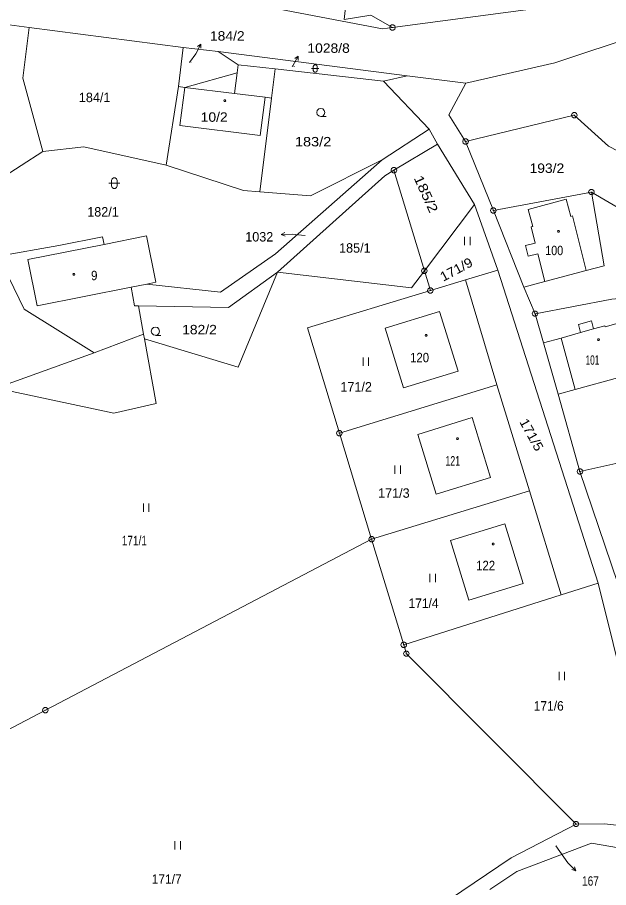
# Model space of a CAD drawing. Extents: x -687390 to -684106, y -954833 to -951648.
# Drawn here: x -686782.5 to -686675.9, y -952530.5 to -952373.7 of the extents above; entities that cross this region are included whole.
import ezdxf
from ezdxf.enums import TextEntityAlignment as Align

# ---------------------------------------------------------------- set-up
doc = ezdxf.new("R2010")
doc.units = 0
doc.header["$LTSCALE"] = 0.68
for name, color, linetype, lineweight in [('1', 7, 'Continuous', 13), ('3', 7, 'Continuous', 13), ('4', 7, 'Continuous', 13), ('5', 7, 'Continuous', 13), ('7', 7, 'Continuous', 13), ('8', 7, 'Continuous', 13)]:
    doc.layers.add(name, color=color, linetype=linetype, lineweight=lineweight)
doc.layers.add('2', color=7, linetype='Continuous')

msp = doc.modelspace()

# ---------------------------------------------------------------- linework, layer by layer
at = {"layer": '1'}
for p, q in [((-686714.84, -952375.47), (-686689.87, -952372.16)), ((-686785.8, -952374.77), (-686780.33, -952375.48)), ((-686753.44, -952386.12), (-686752.56, -952379.08)), ((-686752.56, -952379.08), (-686746.26, -952379.83)), ((-686742.67, -952382.2), (-686746.26, -952379.83)), ((-686746.26, -952379.83), (-686712.18, -952384.17)), ((-686735.98, -952382.95), (-686742.67, -952382.2)), ((-686735.98, -952382.95), (-686736.64, -952388.19)), ((-686716.46, -952385.15), (-686735.98, -952382.95)), ((-686716.46, -952385.15), (-686712.18, -952384.17)), ((-686712.18, -952384.17), (-686701.59, -952385.52)), ((-686755.64, -952400.32), (-686753.44, -952386.12)), ((-686752.26, -952386.27), (-686753.44, -952386.12)), ((-686736.64, -952388.19), (-686738.74, -952405.12)), ((-686696.66, -952408.48), (-686701.66, -952396.03)), ((-686716.7, -952399.34), (-686735.91, -952416.26)), ((-686755.64, -952400.32), (-686741.72, -952404.89)), ((-686738.74, -952405.12), (-686741.72, -952404.89)), ((-686729.62, -952405.8), (-686738.74, -952405.12)), ((-686696.66, -952408.48), (-686678.97, -952405.15)), ((-686676.68, -952418.44), (-686678.97, -952405.15)), ((-686700.05, -952407.36), (-686695.83, -952419.23)), ((-686691.17, -952422.3), (-686696.66, -952408.48)), ((-686757.52, -952421.4), (-686759.18, -952413.05)), ((-686745.82, -952423.17), (-686735.91, -952416.26)), ((-686679.93, -952419.3), (-686676.68, -952418.44)), ((-686708.01, -952422.9), (-686709.09, -952419.35)), ((-686695.83, -952419.23), (-686701.66, -952420.99)), ((-686677.75, -952475.63), (-686695.83, -952419.23)), ((-686679.93, -952419.3), (-686687.37, -952421.27)), ((-686759.11, -952421.72), (-686761.94, -952422.28)), ((-686757.52, -952421.4), (-686759.11, -952421.72)), ((-686745.82, -952423.17), (-686759.11, -952421.72)), ((-686708.01, -952422.9), (-686701.66, -952420.99)), ((-686696.02, -952439.88), (-686701.66, -952420.99)), ((-686691.17, -952422.3), (-686687.37, -952421.27)), ((-686730.19, -952429.61), (-686708.01, -952422.9)), ((-686689.14, -952427.08), (-686691.17, -952422.3)), ((-686706.35, -952426.65), (-686716.17, -952429.66)), ((-686703.03, -952437.43), (-686706.35, -952426.65)), ((-686687.6, -952432.34), (-686689.14, -952427.08)), ((-686730.19, -952429.61), (-686724.41, -952448.64)), ((-686712.85, -952440.45), (-686716.17, -952429.66)), ((-686759.71, -952430.75), (-686759.56, -952431.6)), ((-686687.6, -952432.34), (-686684.45, -952431.47)), ((-686680.92, -952430.44), (-686684.45, -952431.47)), ((-686684.98, -952441.58), (-686687.6, -952432.34)), ((-686703.03, -952437.43), (-686712.85, -952440.45)), ((-686674.02, -952438.55), (-686681.88, -952440.72)), ((-686724.41, -952448.64), (-686696.02, -952439.88)), ((-686690.16, -952458.98), (-686696.02, -952439.88)), ((-686684.98, -952441.58), (-686681.88, -952440.72)), ((-686783.43, -952441.09), (-686765.07, -952445)), ((-686681.04, -952455.54), (-686684.98, -952441.58)), ((-686700.46, -952445.81), (-686710.27, -952448.83)), ((-686697.15, -952456.6), (-686700.46, -952445.81)), ((-686724.41, -952448.64), (-686718.6, -952467.74)), ((-686706.96, -952459.61), (-686710.27, -952448.83)), ((-686697.15, -952456.6), (-686706.96, -952459.61)), ((-686718.6, -952467.74), (-686690.16, -952458.98)), ((-686684.43, -952477.74), (-686690.16, -952458.98)), ((-686694.58, -952464.94), (-686704.4, -952467.96)), ((-686691.27, -952475.71), (-686694.58, -952464.94)), ((-686718.6, -952467.74), (-686712.8, -952486.8)), ((-686677.75, -952475.63), (-686684.43, -952477.74)), ((-686677.75, -952475.63), (-686670.36, -952505.63)), ((-686712.8, -952486.8), (-686684.43, -952477.74)), ((-686676.59, -952519.07), (-686669.07, -952519.85)), ((-686692.45, -952527.64), (-686678.98, -952522.51)), ((-686678.98, -952522.51), (-686662.85, -952525.31)), ((-686692.45, -952527.64), (-686697.29, -952530.86))]:
    msp.add_line(p, q, dxfattribs=at)
for points in [[(-686749.65, -952360.33), (-686724.47, -952370.01), (-686723.22, -952370.73), (-686723.57, -952374.05), (-686718.74, -952373.26)], [(-686752.37, -952366.32), (-686749.13, -952369.49), (-686716.62, -952375.7)], [(-686701.59, -952385.52), (-686685.6, -952381.86), (-686670.21, -952376.71), (-686659.63, -952369.13)], [(-686716.62, -952375.7), (-686714.84, -952375.47), (-686718.74, -952373.26)], [(-686755.64, -952400.32), (-686770.49, -952396.96), (-686777.91, -952397.85), (-686781.5, -952384.63), (-686780.33, -952375.48), (-686752.56, -952379.08)], [(-686752.26, -952386.27), (-686742.85, -952383.66), (-686742.67, -952382.2)], [(-686777.91, -952397.85), (-686789.63, -952405.39), (-686795.83, -952394.62), (-686800.98, -952385.97), (-686807.16, -952383.76), (-686807.44, -952383.88)], [(-686716.46, -952385.15), (-686708.23, -952393.81), (-686716.7, -952399.34), (-686729.62, -952405.8)], [(-686701.59, -952385.52), (-686704.68, -952391.24), (-686701.66, -952396.03)], [(-686701.66, -952396.03), (-686682.06, -952391.3), (-686675.88, -952396.85), (-686665.06, -952402.45)], [(-686708.23, -952393.81), (-686706.7, -952396.5), (-686714.58, -952401.21)], [(-686706.7, -952396.5), (-686700.05, -952407.36), (-686709.09, -952419.35)], [(-686711.42, -952422.44), (-686709.09, -952419.35), (-686714.58, -952401.21), (-686716.24, -952402.2)], [(-686711.42, -952422.44), (-686735.6, -952419.56), (-686716.24, -952402.2)], [(-686665.06, -952402.45), (-686669.41, -952410.76), (-686678.97, -952405.15)], [(-686774.98, -952414.79), (-686767.13, -952413.21), (-686766.84, -952414.57), (-686759.18, -952413.05)], [(-686774.98, -952414.79), (-686785.93, -952416.7), (-686781.27, -952426.24), (-686768.61, -952434.13), (-686786.38, -952440.47)], [(-686735.6, -952419.56), (-686744.41, -952425.95), (-686760.61, -952425.66), (-686759.71, -952430.75)], [(-686759.56, -952431.6), (-686742.64, -952436.7), (-686735.6, -952419.56)], [(-686760.61, -952425.66), (-686761.35, -952425.66), (-686761.94, -952422.28)], [(-686658.17, -952422.97), (-686675.3, -952424.44), (-686689.14, -952427.08)], [(-686670.16, -952437.47), (-686670.75, -952435.33), (-686672.64, -952428.38), (-686676.51, -952429.43), (-686676.56, -952429.24), (-686678.59, -952429.8), (-686678.99, -952428.36), (-686681.31, -952429), (-686680.92, -952430.44)], [(-686759.56, -952431.6), (-686757.45, -952443.26), (-686765.07, -952445)], [(-686659.42, -952450.74), (-686681.04, -952455.54), (-686674.29, -952475.54)], [(-686830.43, -952526.36), (-686777.42, -952498.58), (-686718.6, -952467.74)], [(-686691.27, -952475.71), (-686701.08, -952478.73), (-686704.4, -952467.96)], [(-686712.8, -952486.8), (-686712.33, -952488.37), (-686681.74, -952519.09)], [(-686735.94, -952558.3), (-686715.66, -952540.23), (-686693.42, -952525.17), (-686681.74, -952519.09), (-686676.59, -952519.07)]]:
    msp.add_lwpolyline(points, dxfattribs=at)
at = {"layer": '3'}
for p, q in [((-686701.84, -952413.24), (-686701.84, -952414.74)), ((-686700.84, -952414.74), (-686700.84, -952413.24)), ((-686720.15, -952435), (-686720.15, -952436.5)), ((-686719.15, -952436.5), (-686719.15, -952435)), ((-686714.39, -952454.45), (-686714.39, -952455.95)), ((-686713.39, -952455.95), (-686713.39, -952454.45)), ((-686759.76, -952461.31), (-686759.76, -952462.81)), ((-686758.76, -952462.81), (-686758.76, -952461.31)), ((-686708.08, -952473.98), (-686708.08, -952475.48)), ((-686707.08, -952475.48), (-686707.08, -952473.98)), ((-686684.81, -952491.66), (-686684.81, -952493.16)), ((-686683.81, -952493.16), (-686683.81, -952491.66)), ((-686754.09, -952522.18), (-686754.09, -952523.68)), ((-686753.09, -952523.68), (-686753.09, -952522.18))]:
    msp.add_line(p, q, dxfattribs=at)
for points in [[(-686729.45, -952382.87), (-686728.599, -952382.87), (-686728.11, -952382.87)], [(-686727.76, -952391.53), (-686728.14, -952391.43), (-686728.41, -952391.16), (-686728.51, -952390.79), (-686728.41, -952390.42), (-686728.14, -952390.15), (-686727.77, -952390.05), (-686727.4, -952390.15), (-686727.13, -952390.42), (-686727.03, -952390.8), (-686727.13, -952391.18), (-686727.4, -952391.45), (-686727.78, -952391.55), (-686726.78, -952391.55)], [(-686765.98, -952403.54), (-686764.71, -952403.54), (-686763.98, -952403.54)], [(-686757.57, -952430.97), (-686757.95, -952430.87), (-686758.22, -952430.6), (-686758.32, -952430.23), (-686758.22, -952429.86), (-686757.95, -952429.59), (-686757.58, -952429.49), (-686757.21, -952429.59), (-686756.94, -952429.86), (-686756.84, -952430.24), (-686756.94, -952430.62), (-686757.21, -952430.89), (-686757.59, -952430.99), (-686756.59, -952430.99)]]:
    msp.add_lwpolyline(points, dxfattribs=at)
for points in [[(-686729.115, -952382.535), (-686729.048, -952382.341), (-686728.88, -952382.22), (-686728.673, -952382.22), (-686728.505, -952382.341), (-686728.438, -952382.535), (-686728.438, -952383.205), (-686728.505, -952383.399), (-686728.673, -952383.52), (-686728.88, -952383.52), (-686729.048, -952383.399), (-686729.115, -952383.205)], [(-686765.48, -952403.04), (-686765.38, -952402.75), (-686765.13, -952402.57), (-686764.82, -952402.57), (-686764.57, -952402.75), (-686764.47, -952403.04), (-686764.47, -952404.04), (-686764.57, -952404.33), (-686764.82, -952404.51), (-686765.13, -952404.51), (-686765.38, -952404.33), (-686765.48, -952404.04)]]:
    msp.add_lwpolyline(points, close=True, dxfattribs=at)
at = {"layer": '4'}
for p, q in [((-686743.31, -952387.37), (-686742.85, -952383.66)), ((-686752.26, -952386.27), (-686743.31, -952387.37)), ((-686743.31, -952387.37), (-686737.77, -952388.05)), ((-686737.77, -952388.05), (-686736.64, -952388.19)), ((-686761.94, -952422.28), (-686778.91, -952425.66)), ((-686678.59, -952429.8), (-686680.92, -952430.44)), ((-686768.61, -952434.13), (-686759.71, -952430.75)), ((-686684.45, -952431.47), (-686681.88, -952440.72))]:
    msp.add_line(p, q, dxfattribs=at)
for points in [[(-686737.77, -952388.05), (-686738.7, -952394.95), (-686753.2, -952393.16), (-686752.26, -952386.27)], [(-686687.37, -952421.27), (-686688.64, -952416.28), (-686690.38, -952416.72), (-686690.88, -952414.77), (-686689.12, -952414.34), (-686689.86, -952411.44), (-686689.56, -952411.36), (-686690.38, -952408.26), (-686683.52, -952406.43), (-686682.7, -952409.53), (-686682.41, -952409.45), (-686679.93, -952419.3)], [(-686778.91, -952425.66), (-686780.58, -952417.31), (-686766.84, -952414.57)]]:
    msp.add_lwpolyline(points, dxfattribs=at)
at = {"layer": '5'}
for points in [[(-686744.98, -952388.52), (-686744.89, -952388.67), (-686744.98, -952388.82), (-686745.16, -952388.82), (-686745.25, -952388.67), (-686745.16, -952388.52)], [(-686684.8, -952412.07), (-686684.71, -952412.22), (-686684.8, -952412.37), (-686684.98, -952412.37), (-686685.07, -952412.22), (-686684.98, -952412.07)], [(-686772.18, -952419.8), (-686772.09, -952419.95), (-686772.18, -952420.1), (-686772.36, -952420.1), (-686772.45, -952419.95), (-686772.36, -952419.8)], [(-686708.7, -952430.83), (-686708.61, -952430.98), (-686708.7, -952431.13), (-686708.88, -952431.13), (-686708.97, -952430.98), (-686708.88, -952430.83)], [(-686677.6, -952431.62), (-686677.51, -952431.77), (-686677.6, -952431.92), (-686677.78, -952431.92), (-686677.87, -952431.77), (-686677.78, -952431.62)], [(-686703.01, -952449.48), (-686702.92, -952449.63), (-686703.01, -952449.78), (-686703.19, -952449.78), (-686703.28, -952449.63), (-686703.19, -952449.48)], [(-686696.58, -952468.46), (-686696.49, -952468.61), (-686696.58, -952468.76), (-686696.76, -952468.76), (-686696.85, -952468.61), (-686696.76, -952468.46)]]:
    msp.add_lwpolyline(points, close=True, dxfattribs=at)
at = {"layer": '7'}
for p, q in [((-686749.367, -952378.48), (-686750.32, -952380.25)), ((-686751.45, -952381.77), (-686750.32, -952380.25)), ((-686731.821, -952380.662), (-686732.83, -952382.4)), ((-686732.93, -952382.53), (-686732.83, -952382.4)), ((-686734.89, -952412.769), (-686732.88, -952412.73)), ((-686730.72, -952413), (-686732.88, -952412.73)), ((-686685.39, -952523.03), (-686683.2, -952526.07)), ((-686681.806, -952527.518), (-686683.2, -952526.07))]:
    msp.add_line(p, q, dxfattribs=at)
for points in [[(-686749.979, -952378.911), (-686749.367, -952378.48), (-686749.389, -952379.229)], [(-686732.447, -952381.073), (-686731.821, -952380.662), (-686731.867, -952381.41)], [(-686734.213, -952413.091), (-686734.89, -952412.769), (-686734.226, -952412.421)], [(-686682.029, -952526.803), (-686681.806, -952527.518), (-686682.512, -952527.268)]]:
    msp.add_lwpolyline(points, dxfattribs=at)
at = {"layer": '8'}
for p, q in [((-686714.96, -952375.47), (-686714.72, -952375.47)), ((-686682.18, -952391.3), (-686681.94, -952391.3)), ((-686701.78, -952396.03), (-686701.54, -952396.03)), ((-686714.7, -952401.21), (-686714.46, -952401.21)), ((-686679.09, -952405.15), (-686678.85, -952405.15)), ((-686696.78, -952408.48), (-686696.54, -952408.48)), ((-686709.21, -952419.35), (-686708.97, -952419.35)), ((-686708.13, -952422.9), (-686707.89, -952422.9)), ((-686689.26, -952427.08), (-686689.02, -952427.08)), ((-686724.53, -952448.64), (-686724.29, -952448.64)), ((-686681.16, -952455.54), (-686680.92, -952455.54)), ((-686681.16, -952455.54), (-686680.92, -952455.54)), ((-686718.72, -952467.74), (-686718.48, -952467.74)), ((-686712.92, -952486.8), (-686712.68, -952486.8)), ((-686712.45, -952488.37), (-686712.21, -952488.37)), ((-686777.54, -952498.58), (-686777.3, -952498.58)), ((-686681.86, -952519.09), (-686681.62, -952519.09))]:
    msp.add_line(p, q, dxfattribs=at)
for points in [[(-686714.69, -952374.99), (-686714.44, -952375.17), (-686714.34, -952375.46), (-686714.44, -952375.75), (-686714.69, -952375.93), (-686715, -952375.93), (-686715.25, -952375.75), (-686715.35, -952375.46), (-686715.25, -952375.17), (-686715, -952374.99)], [(-686681.91, -952390.82), (-686681.66, -952391), (-686681.56, -952391.29), (-686681.66, -952391.58), (-686681.91, -952391.76), (-686682.22, -952391.76), (-686682.47, -952391.58), (-686682.57, -952391.29), (-686682.47, -952391), (-686682.22, -952390.82)], [(-686701.51, -952395.55), (-686701.26, -952395.73), (-686701.16, -952396.02), (-686701.26, -952396.31), (-686701.51, -952396.49), (-686701.82, -952396.49), (-686702.07, -952396.31), (-686702.17, -952396.02), (-686702.07, -952395.73), (-686701.82, -952395.55)], [(-686714.43, -952400.73), (-686714.18, -952400.91), (-686714.08, -952401.2), (-686714.18, -952401.49), (-686714.43, -952401.67), (-686714.74, -952401.67), (-686714.99, -952401.49), (-686715.09, -952401.2), (-686714.99, -952400.91), (-686714.74, -952400.73)], [(-686678.82, -952404.67), (-686678.57, -952404.85), (-686678.47, -952405.14), (-686678.57, -952405.43), (-686678.82, -952405.61), (-686679.13, -952405.61), (-686679.38, -952405.43), (-686679.48, -952405.14), (-686679.38, -952404.85), (-686679.13, -952404.67)], [(-686696.51, -952408), (-686696.26, -952408.18), (-686696.16, -952408.47), (-686696.26, -952408.76), (-686696.51, -952408.94), (-686696.82, -952408.94), (-686697.07, -952408.76), (-686697.17, -952408.47), (-686697.07, -952408.18), (-686696.82, -952408)], [(-686708.94, -952418.87), (-686708.69, -952419.05), (-686708.59, -952419.34), (-686708.69, -952419.63), (-686708.94, -952419.81), (-686709.25, -952419.81), (-686709.5, -952419.63), (-686709.6, -952419.34), (-686709.5, -952419.05), (-686709.25, -952418.87)], [(-686707.86, -952422.42), (-686707.61, -952422.6), (-686707.51, -952422.89), (-686707.61, -952423.18), (-686707.86, -952423.36), (-686708.17, -952423.36), (-686708.42, -952423.18), (-686708.52, -952422.89), (-686708.42, -952422.6), (-686708.17, -952422.42)], [(-686688.99, -952426.6), (-686688.74, -952426.78), (-686688.64, -952427.07), (-686688.74, -952427.36), (-686688.99, -952427.54), (-686689.3, -952427.54), (-686689.55, -952427.36), (-686689.65, -952427.07), (-686689.55, -952426.78), (-686689.3, -952426.6)], [(-686724.26, -952448.16), (-686724.01, -952448.34), (-686723.91, -952448.63), (-686724.01, -952448.92), (-686724.26, -952449.1), (-686724.57, -952449.1), (-686724.82, -952448.92), (-686724.92, -952448.63), (-686724.82, -952448.34), (-686724.57, -952448.16)], [(-686680.89, -952455.06), (-686680.64, -952455.24), (-686680.54, -952455.53), (-686680.64, -952455.82), (-686680.89, -952456), (-686681.2, -952456), (-686681.45, -952455.82), (-686681.55, -952455.53), (-686681.45, -952455.24), (-686681.2, -952455.06)], [(-686680.89, -952455.06), (-686680.64, -952455.24), (-686680.54, -952455.53), (-686680.64, -952455.82), (-686680.89, -952456), (-686681.2, -952456), (-686681.45, -952455.82), (-686681.55, -952455.53), (-686681.45, -952455.24), (-686681.2, -952455.06)], [(-686718.45, -952467.26), (-686718.2, -952467.44), (-686718.1, -952467.73), (-686718.2, -952468.02), (-686718.45, -952468.2), (-686718.76, -952468.2), (-686719.01, -952468.02), (-686719.11, -952467.73), (-686719.01, -952467.44), (-686718.76, -952467.26)], [(-686712.65, -952486.32), (-686712.4, -952486.5), (-686712.3, -952486.79), (-686712.4, -952487.08), (-686712.65, -952487.26), (-686712.96, -952487.26), (-686713.21, -952487.08), (-686713.31, -952486.79), (-686713.21, -952486.5), (-686712.96, -952486.32)], [(-686712.18, -952487.89), (-686711.93, -952488.07), (-686711.83, -952488.36), (-686711.93, -952488.65), (-686712.18, -952488.83), (-686712.49, -952488.83), (-686712.74, -952488.65), (-686712.84, -952488.36), (-686712.74, -952488.07), (-686712.49, -952487.89)], [(-686777.27, -952498.1), (-686777.02, -952498.28), (-686776.92, -952498.57), (-686777.02, -952498.86), (-686777.27, -952499.04), (-686777.58, -952499.04), (-686777.83, -952498.86), (-686777.93, -952498.57), (-686777.83, -952498.28), (-686777.58, -952498.1)], [(-686681.59, -952518.61), (-686681.34, -952518.79), (-686681.24, -952519.08), (-686681.34, -952519.37), (-686681.59, -952519.55), (-686681.9, -952519.55), (-686682.15, -952519.37), (-686682.25, -952519.08), (-686682.15, -952518.79), (-686681.9, -952518.61)]]:
    msp.add_lwpolyline(points, close=True, dxfattribs=at)

# ---------------------------------------------------------------- texts
at = {"layer": '2'}
for s, height, width, p in [('184/2', 0.1, 1.1, (-686751.404, -952381.77)), ('1028/8', 0.1, 1.1, (-686732.884, -952382.53)), ('10/2', 1.7, 1.1, (-686749.425, -952392.47)), ('183/2', 1.7, 1.15, (-686732.425, -952396.91)), ('193/2', 1.7, 1.1, (-686690.135, -952401.69)), ('100', 1.7, 0.85, (-686687.295, -952416.52)), ('9', 1.7, 0.9, (-686769.175, -952421.04)), ('182/2', 1.7, 1.1, (-686752.765, -952430.79)), ('120', 1.7, 0.9, (-686711.665, -952435.83)), ('101', 1.7, 0.65, (-686680.025, -952436.28)), ('121', 1.7, 0.7, (-686705.305, -952454.45)), ('171/1', 1.7, 0.8, (-686763.655, -952468.82)), ('122', 1.7, 0.9, (-686699.755, -952473.32)), ('171/4', 1.7, 0.95, (-686711.945, -952480.12)), ('171/6', 1.7, 0.95, (-686689.375, -952498.63)), ('167', 0.1, 0.8, (-686685.344, -952523.03)), ('171/7', 1.7, 0.95, (-686758.255, -952529.86))]:
    msp.add_text(s, height=height, dxfattribs=dict(at, width=width)).set_placement(p)
for s, height, p in [('184/1', 1.7, (-686771.385, -952388.93)), ('182/1', 1.7, (-686769.875, -952409.56)), ('1032', 0.1, (-686730.674, -952413)), ('185/1', 1.7, (-686724.475, -952416.07)), ('171/2', 1.7, (-686724.235, -952441.11)), ('171/3', 1.7, (-686717.435, -952460.26))]:
    msp.add_text(s, height=height, dxfattribs=at).set_placement(p)
for s, rotation, width, p in [('185/2', 294.443, 1.25, (-686711.045, -952402.605)), ('171/9', 28.361, 1.1, (-686705.689, -952421.327)), ('171/5', 298.855, 1.1, (-686692.021, -952446.558))]:
    msp.add_text(s, height=1.7, rotation=rotation, dxfattribs=dict(at, width=width)).set_placement(p)
at = {"layer": '7'}
for s, width, p in [('184/2', 1.1, (-686747.755, -952377.84)), ('1028/8', 1.1, (-686730.185, -952380.04)), ('167', 0.8, (-686680.665, -952530.2))]:
    msp.add_text(s, height=1.7, dxfattribs=dict(at, width=width)).set_placement(p)
msp.add_text('1032', height=1.7, dxfattribs=at).set_placement((-686736.336, -952414.06), align=Align.RIGHT)

doc.saveas('drawing.dxf')
